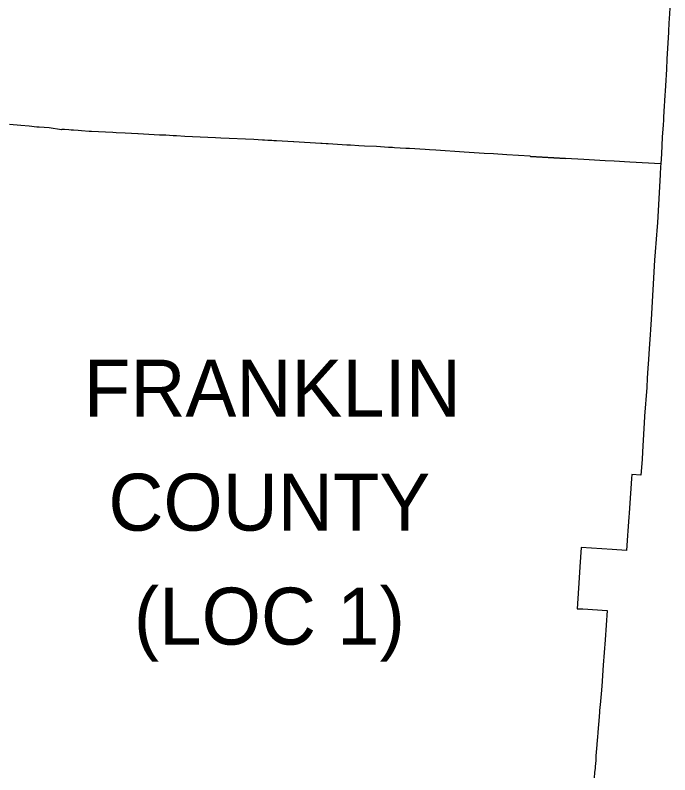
# Model space of a CAD drawing. Extents: x 0 to 34, y 0 to 22.
# Drawn here: x 5.53 to 7.055, y 16.5 to 18.27 of the extents above; entities that cross this region are included whole.
import ezdxf

# ---------------------------------------------------------------- set-up
doc = ezdxf.new("R2010")
doc.units = 0
doc.layers.add('GM_X_County', color=7, linetype='Continuous')
doc.layers.add('SH_Data', color=7, linetype='Continuous')

msp = doc.modelspace()

# ---------------------------------------------------------------- linework, layer by layer
at = {"layer": 'GM_X_County'}
for p, q in [((7.0546, 18.2864), (7.0532, 18.2617)), ((7.0526, 18.2525), (7.0516, 18.2323)), ((7.0532, 18.2617), (7.0526, 18.2525)), ((7.0514, 18.2309), (7.048, 18.1678)), ((7.0516, 18.2323), (7.0514, 18.2309)), ((7.048, 18.1678), (7.0467, 18.1445)), ((7.0467, 18.1445), (7.0445, 18.1055)), ((7.0445, 18.1055), (7.0424, 18.0712)), ((7.0416, 18.0593), (7.04, 18.033)), ((7.0423, 18.0701), (7.0416, 18.0593)), ((7.0424, 18.0712), (7.0423, 18.0701)), ((7.0396, 18.0257), (7.0389, 18.0147)), ((7.04, 18.033), (7.0396, 18.0257)), ((5.5424, 18.0131), (5.5163, 18.0153)), ((5.5619, 18.0115), (5.5424, 18.0131)), ((5.5802, 18.0096), (5.5619, 18.0115)), ((5.5856, 18.0094), (5.5802, 18.0096)), ((5.6089, 18.0074), (5.5856, 18.0094)), ((5.6372, 18.0034), (5.6089, 18.0074)), ((7.0389, 18.0147), (7.0371, 17.9858)), ((5.6384, 18.004), (5.6372, 18.0034)), ((5.6396, 18.0042), (5.6384, 18.004)), ((5.6407, 18.004), (5.6396, 18.0042)), ((5.6445, 18.0038), (5.6407, 18.004)), ((5.6548, 18.003), (5.6445, 18.0038)), ((5.6597, 18.0026), (5.6548, 18.003)), ((5.6652, 18.0022), (5.6597, 18.0026)), ((5.6763, 18.0014), (5.6652, 18.0022)), ((5.6839, 18.0007), (5.6763, 18.0014)), ((5.7019, 17.999), (5.6839, 18.0007)), ((5.7074, 17.999), (5.7019, 17.999)), ((5.7401, 17.9974), (5.7074, 17.999)), ((5.7567, 17.9967), (5.7401, 17.9974)), ((5.7644, 17.9963), (5.7567, 17.9967)), ((5.7854, 17.995), (5.7644, 17.9963)), ((5.8154, 17.9938), (5.7854, 17.995)), ((5.8163, 17.9938), (5.8154, 17.9938)), ((5.8659, 17.991), (5.8163, 17.9938)), ((5.8807, 17.9904), (5.8659, 17.991)), ((5.8972, 17.9893), (5.8807, 17.9904)), ((5.905, 17.9889), (5.8972, 17.9893)), ((5.9246, 17.9879), (5.905, 17.9889)), ((5.9959, 17.9842), (5.9246, 17.9879)), ((5.9963, 17.9842), (5.9959, 17.9842)), ((6.0083, 17.9839), (5.9963, 17.9842)), ((6.0088, 17.9839), (6.0083, 17.9839)), ((6.0852, 17.9803), (6.0088, 17.9839)), ((6.0856, 17.9802), (6.0852, 17.9803)), ((6.1057, 17.9791), (6.0856, 17.9802)), ((6.1091, 17.979), (6.1057, 17.9791)), ((6.1103, 17.979), (6.1091, 17.979)), ((6.1183, 17.9786), (6.1103, 17.979)), ((6.1272, 17.9781), (6.1183, 17.9786)), ((6.1318, 17.9778), (6.1272, 17.9781)), ((6.1385, 17.9774), (6.1318, 17.9778)), ((6.1781, 17.9749), (6.1385, 17.9774)), ((6.1788, 17.9748), (6.1781, 17.9749)), ((6.2418, 17.9713), (6.1788, 17.9748)), ((6.2449, 17.971), (6.2418, 17.9713)), ((6.2542, 17.9703), (6.2449, 17.971)), ((6.2587, 17.9701), (6.2542, 17.9703)), ((6.3021, 17.9677), (6.2587, 17.9701)), ((7.0371, 17.9858), (7.0349, 17.9475)), ((6.3068, 17.9674), (6.3021, 17.9677)), ((6.311, 17.9671), (6.3068, 17.9674)), ((6.3301, 17.9661), (6.311, 17.9671)), ((6.3434, 17.9654), (6.3301, 17.9661)), ((6.3711, 17.9639), (6.3434, 17.9654)), ((6.3992, 17.9623), (6.3711, 17.9639)), ((6.4062, 17.9619), (6.3992, 17.9623)), ((6.4087, 17.9617), (6.4062, 17.9619)), ((6.4128, 17.9615), (6.4087, 17.9617)), ((6.4392, 17.9599), (6.4128, 17.9615)), ((6.4415, 17.9598), (6.4392, 17.9599)), ((6.4436, 17.9596), (6.4415, 17.9598)), ((6.4475, 17.9594), (6.4436, 17.9596)), ((6.448, 17.9594), (6.4475, 17.9594)), ((6.4845, 17.9573), (6.448, 17.9594)), ((6.4947, 17.9567), (6.4845, 17.9573)), ((6.5094, 17.9558), (6.4947, 17.9567)), ((6.5757, 17.9514), (6.5094, 17.9558)), ((6.6221, 17.9482), (6.5757, 17.9514)), ((6.6435, 17.9468), (6.6221, 17.9482)), ((6.6751, 17.9446), (6.6435, 17.9468)), ((6.7294, 17.9414), (6.6751, 17.9446)), ((6.7301, 17.9413), (6.7294, 17.9414)), ((6.8113, 17.9366), (6.7301, 17.9413)), ((6.7301, 17.9413), (6.7308, 17.9413)), ((6.7308, 17.9413), (6.8113, 17.9366)), ((6.8541, 17.9341), (6.8113, 17.9366)), ((6.9041, 17.9312), (6.8541, 17.9341)), ((7.0349, 17.9475), (7.0335, 17.924)), ((6.9251, 17.93), (6.9041, 17.9312)), ((6.9618, 17.9277), (6.9251, 17.93)), ((7.0335, 17.924), (6.9618, 17.9277)), ((7.0331, 17.9175), (7.0319, 17.8989)), ((7.0335, 17.924), (7.0331, 17.9175)), ((7.0319, 17.8989), (7.0257, 17.7864)), ((7.0251, 17.7781), (7.0203, 17.7186)), ((7.0252, 17.7783), (7.0251, 17.7781)), ((7.0253, 17.7789), (7.0252, 17.7783)), ((7.0256, 17.7858), (7.0253, 17.7789)), ((7.0257, 17.7864), (7.0256, 17.7858)), ((7.0203, 17.7186), (7.0191, 17.6994)), ((7.0191, 17.6994), (7.0111, 17.5612)), ((7.0111, 17.5612), (7.0095, 17.5381)), ((7.0095, 17.5381), (7.0087, 17.5252)), ((7.0087, 17.5252), (7.0067, 17.4932)), ((7.0067, 17.4932), (7.0049, 17.4678)), ((7.0049, 17.4678), (7.0034, 17.4475)), ((7.0034, 17.4475), (7.0019, 17.424)), ((7.0019, 17.424), (7.0007, 17.4027)), ((7.0007, 17.4027), (6.9959, 17.3361)), ((6.9958, 17.3341), (6.9911, 17.2528)), ((6.9959, 17.3361), (6.9958, 17.3341)), ((6.9911, 17.2528), (6.9899, 17.2349)), ((6.9899, 17.2349), (6.9874, 17.1979)), ((6.966, 17.1998), (6.9653, 17.1902)), ((6.9874, 17.1979), (6.966, 17.1998)), ((6.9653, 17.1902), (6.9605, 17.1213)), ((6.9605, 17.1213), (6.9597, 17.1097)), ((6.9597, 17.1097), (6.959, 17.1002)), ((6.959, 17.1002), (6.9568, 17.0686)), ((6.9568, 17.0686), (6.9561, 17.0577)), ((6.9561, 17.0577), (6.9536, 17.0224)), ((6.8484, 17.0296), (6.8453, 16.9843)), ((6.92, 17.0247), (6.8484, 17.0296)), ((6.9536, 17.0224), (6.92, 17.0247)), ((6.8453, 16.9843), (6.8436, 16.9588)), ((6.8436, 16.9588), (6.8386, 16.8869)), ((6.8386, 16.8869), (6.8463, 16.8867)), ((6.8463, 16.8867), (6.8519, 16.8864)), ((6.8519, 16.8864), (6.9086, 16.8825)), ((6.9086, 16.8825), (6.9036, 16.8142)), ((6.9036, 16.8142), (6.8992, 16.7553)), ((6.8992, 16.7553), (6.8968, 16.7191)), ((6.8968, 16.7184), (6.8959, 16.7064)), ((6.8968, 16.7191), (6.8968, 16.7184)), ((6.8959, 16.7064), (6.8946, 16.6887)), ((6.8946, 16.6887), (6.8933, 16.6712)), ((6.8919, 16.6592), (6.8899, 16.6352)), ((6.8924, 16.6604), (6.8919, 16.6592)), ((6.8927, 16.663), (6.8924, 16.6604)), ((6.8933, 16.6712), (6.8927, 16.663)), ((6.8899, 16.6352), (6.887, 16.5993)), ((6.887, 16.5993), (6.8859, 16.5865)), ((6.8848, 16.5733), (6.8846, 16.5695)), ((6.8851, 16.5774), (6.8848, 16.5733)), ((6.8856, 16.5814), (6.8851, 16.5774)), ((6.8859, 16.5865), (6.8856, 16.5814)), ((6.8846, 16.5695), (6.8823, 16.5443)), ((6.8821, 16.5354), (6.8819, 16.5335)), ((6.8823, 16.5443), (6.882, 16.5371)), ((6.882, 16.5371), (6.8821, 16.5365)), ((6.8821, 16.5365), (6.8821, 16.5354)), ((6.8807, 16.5192), (6.8803, 16.5148)), ((6.8819, 16.5335), (6.8807, 16.5192)), ((6.8795, 16.5053), (6.8785, 16.4932)), ((6.88, 16.5104), (6.8795, 16.5053)), ((6.8803, 16.5148), (6.88, 16.5104))]:
    msp.add_line(p, q, dxfattribs=at)

# ---------------------------------------------------------------- texts
at = {"layer": 'SH_Data'}
for s, p in [('FRANKLIN', (5.6895, 17.3346)), ('COUNTY', (5.7466, 17.0689)), ('(LOC 1)', (5.8059, 16.8033))]:
    msp.add_text(s, height=0.13282, dxfattribs=at).set_placement(p)

doc.saveas('drawing.dxf')
